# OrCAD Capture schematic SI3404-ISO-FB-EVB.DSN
size B; title: Si3402 Eval Board - Isolated; rev: 2.0; note: SI3404-ISO-FB-EVB
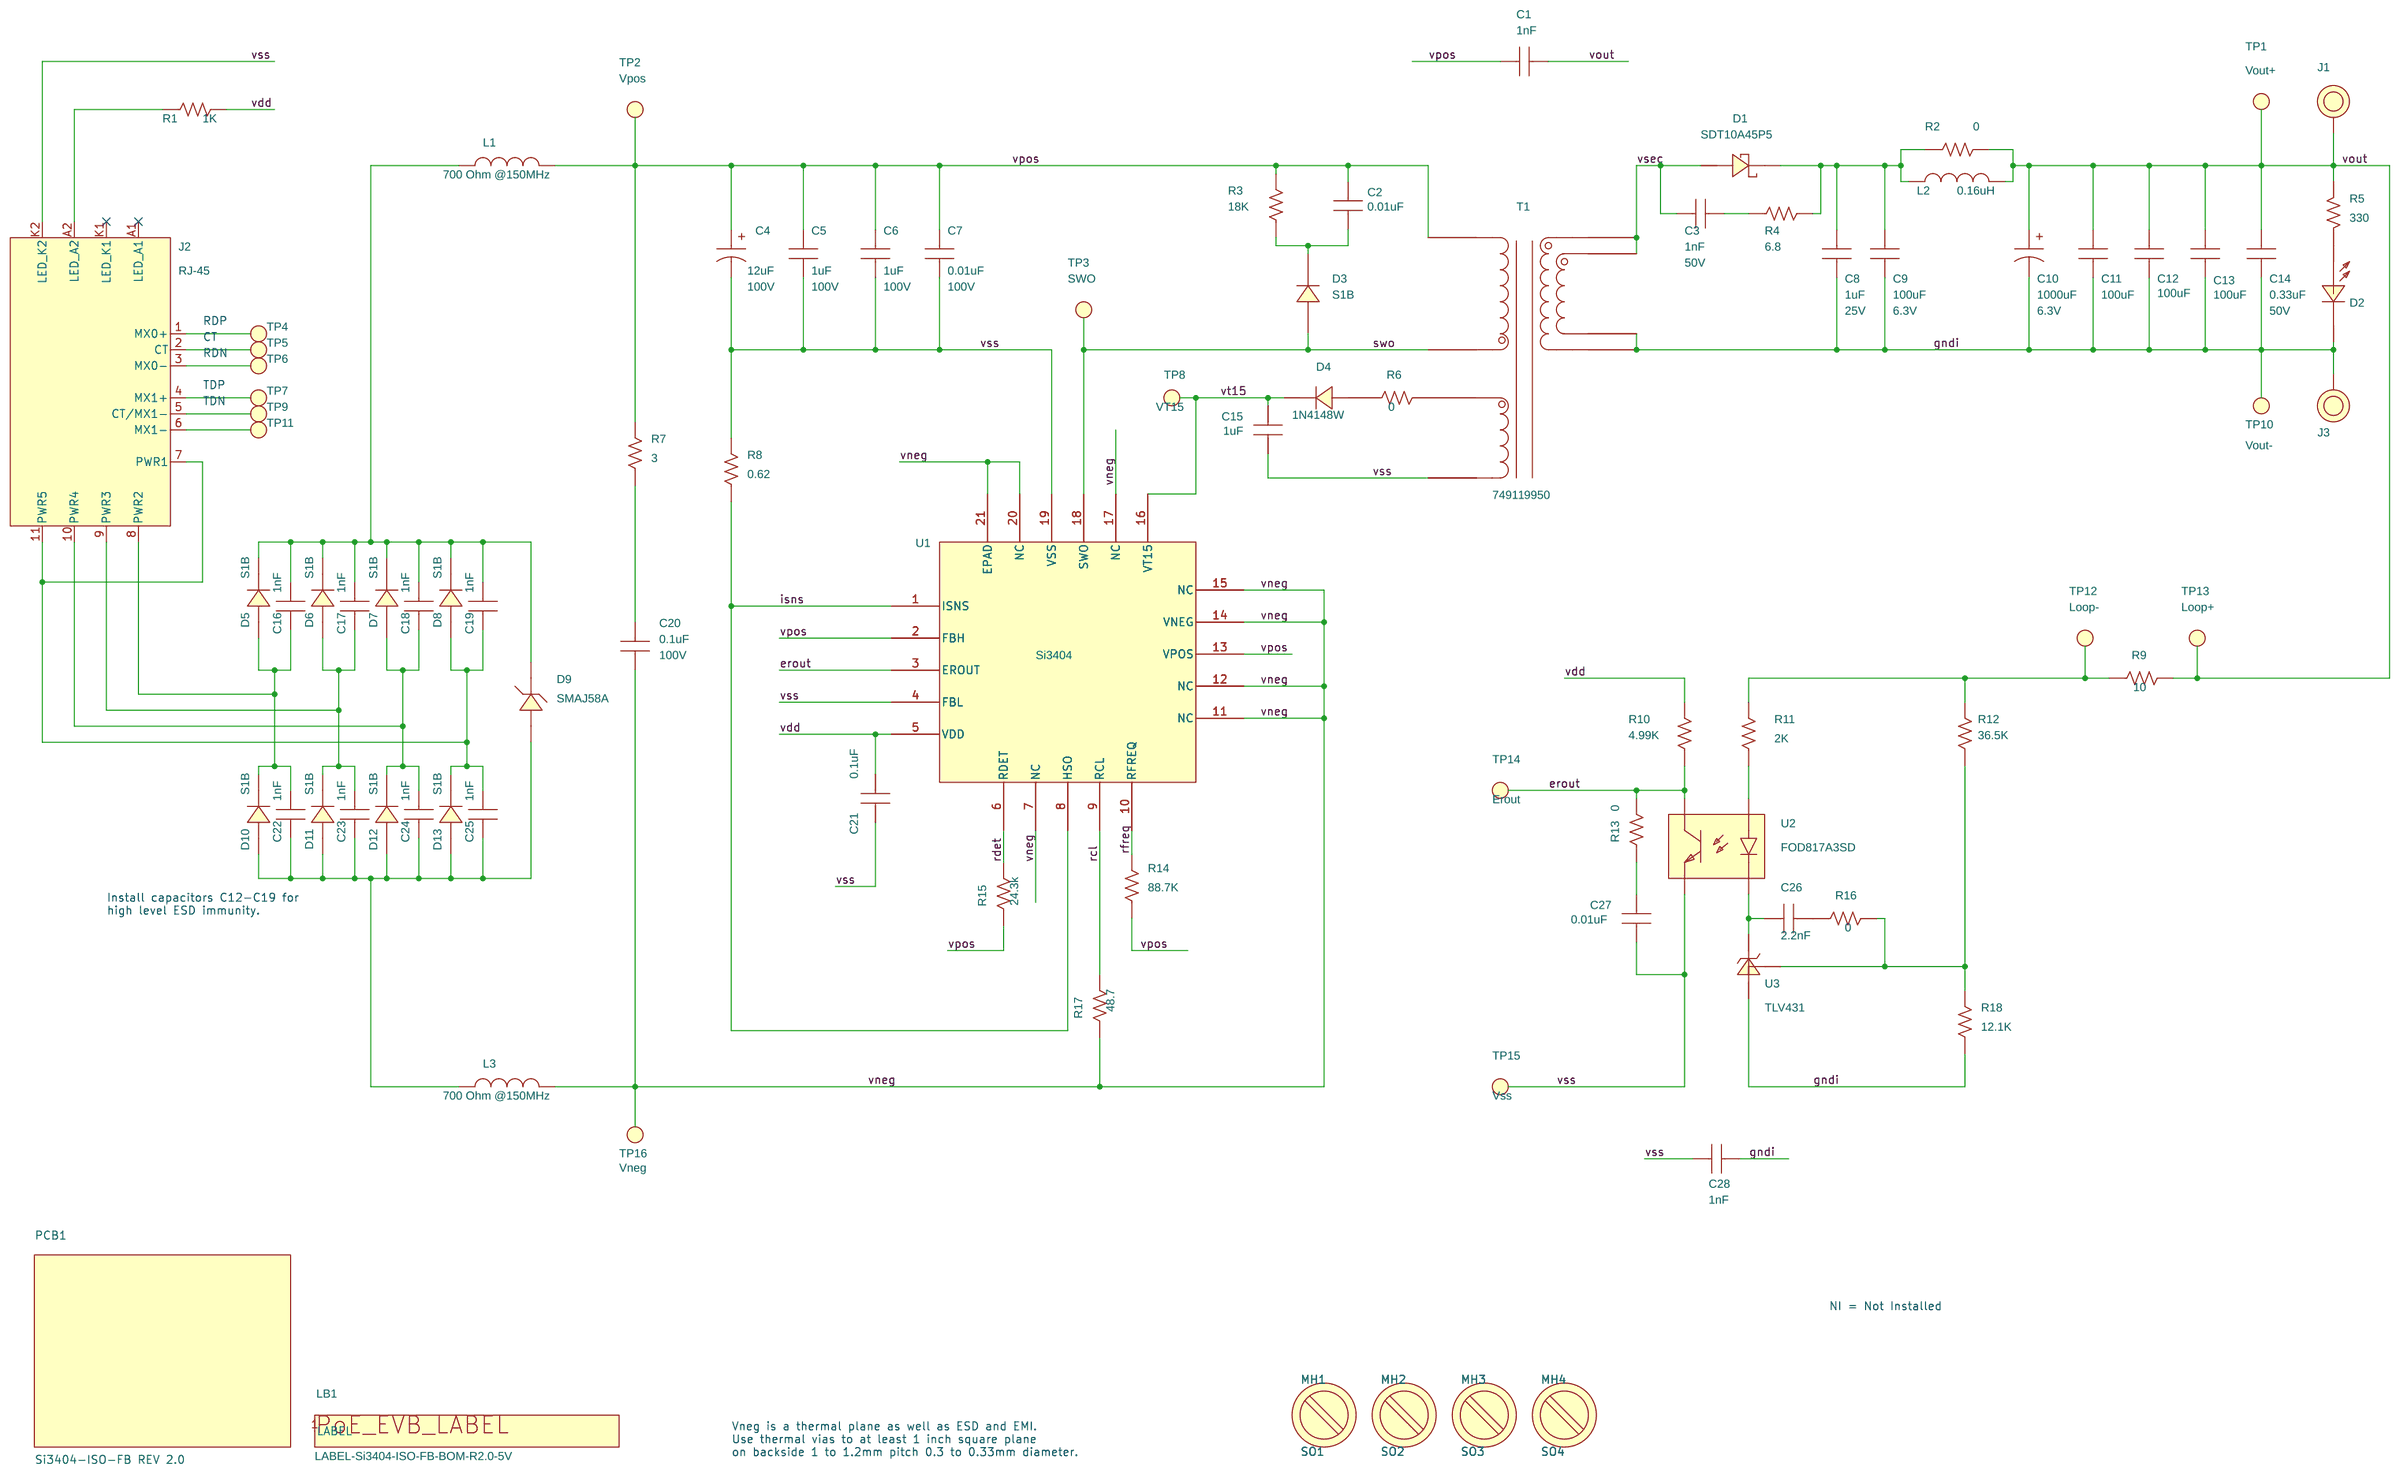
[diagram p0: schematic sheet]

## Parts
C1  1nF  [C1808]
C2  0.01uF  [C0805]
C3  1nF  [C0805]
C4  12uF  [C2.5X6.3MM-RAD]
C5  1uF  [C1210]
C6  1uF  [C1210]
C7  0.01uF  [C0603]
C8  1uF  [C0603]
C9  100uF  [C1210]
C10  1000uF  [C3.5X8MM-RAD]
C11  100uF  [C1210]
C12  100uF  [C1210]
C13  100uF  [C1210]
C14  0.33uF  [C0805]
C15  1uF  [C0805]
C16  1nF  [C0603]
C17  1nF  [C0603]
C18  1nF  [C0603]
C19  1nF  [C0603]
C20  0.1uF  [C0805]
C21  0.1uF  [C0805]
C22  1nF  [C0603]
C23  1nF  [C0603]
C24  1nF  [C0603]
C25  1nF  [C0603]
C26  2.2nF  [C0805]
C27  0.01uF  [C0805]
C28  1nF  [C1808]
D1  SDT10A45P5  [POWERDI-5]
D2  GREEN  [LED-0805-K]
D3  S1B  [DO-214AC]
D4  1N4148W  [SOD-123]
D5  S1B  [DO-214AC]
D6  S1B  [DO-214AC]
D7  S1B  [DO-214AC]
D8  S1B  [DO-214AC]
D9  SMAJ58A  [DO-214AC]
D10  S1B  [DO-214AC]
D11  S1B  [DO-214AC]
D12  S1B  [DO-214AC]
D13  S1B  [DO-214AC]
J1  BND_POST  [BANANA-JACK]
J2  RJ-45  [RJ45-SI-52004]
J3  BND_POST  [BANANA-JACK]
L1  742792040  [L0805]
L2  0.16uH  [IND-XAL50xx]
L3  742792040  [L0805]
LB1  LABEL-Si3404-ISO-FB-BOM-R2.0-5V  [PTL-14-717]
MH1  4-40  [MH-125NP]
MH2  4-40  [MH-125NP]
MH3  4-40  [MH-125NP]
MH4  4-40  [MH-125NP]
PCB1  Si3404-ISO-FB REV 2.0  [N/A]
R1  1K  [R0805]
R2  0  [R0805]
R3  18K  [R0805]
R4  6.8  [R0805]
R5  330  [R0805]
R6  0  [R0805]
R7  3  [R0805]
R8  0.62  [R0805]
R9  10  [R0805]
R10  4.99K  [R0805]
R11  2K  [R0805]
R12  36.5K  [R0805]
R13  0  [R0805]
R14  88.7K  [R0805]
R15  24.3k  [R0805]
R16  0  [R0805]
R17  48.7  [R0805]
R18  12.1K  [R0805]
SO1  STANDOFF
SO2  STANDOFF
SO3  STANDOFF
SO4  STANDOFF
T1  127uH  [XFMR-749119950]
TP1  BLACK  [TESTPOINT]
TP2  BLACK  [TESTPOINT]
TP3  BLACK  [TESTPOINT]
TP4  BLACK  [TESTPOINT]
TP5  BLACK  [TESTPOINT]
TP6  BLACK  [TESTPOINT]
TP7  BLACK  [TESTPOINT]
TP8  BLACK  [TESTPOINT]
TP9  BLACK  [TESTPOINT]
TP10  BLACK  [TESTPOINT]
TP11  BLACK  [TESTPOINT]
TP12  BLACK  [TESTPOINT]
TP13  BLACK  [TESTPOINT]
TP14  BLACK  [TESTPOINT]
TP15  BLACK  [TESTPOINT]
TP16  BLACK  [TESTPOINT]
U1  Si3404  [QFN20M4X4P0.5]
U2  FOD817A3SD  [SO4N10.16P2.54-AKEC]
U3  TLV431  [TLV431-DBZ]

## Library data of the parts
C1 C28 = CAP_NP: CAP, 1nF, 3000V, ±10%, X7R, 1808; Manufacturer: Venkel; ManufacturerPN: C1808X7R302-102K; SiLabsPN: C1808X7R302-102K; Tolerance: ±10%; Type: X7R; Voltage: 3000V; Datasheet: PID_C.pdf
C2 C27 = CAP_NP: CAP, 0.01uF, 100V, ±10%, X7R, 0805; Manufacturer: Venkel; ManufacturerPN: C0805X7R101-103K; SiLabsPN: C0805X7R101-103K; Tolerance: ±10%; Type: X7R; Voltage: 100V; Datasheet: PID_C.pdf
C3 = CAP_NP: CAP, 1nF, 50V, ±1%, C0G, 0805; Manufacturer: Venkel; ManufacturerPN: C0805C0G500-102F; SiLabsPN: C0805C0G500-102F; Tolerance: ±1%; Type: C0G; Voltage: 50V; Datasheet: PID_C.pdf
C4 = CAP_POL_ALT: CAP, 12uF, 100V, ±20%, AL, 6.3X11.2MM; Manufacturer: Panasonic; ManufacturerPN: EEUFC2A120; SiLabsPN: EEUFC2A120; Tolerance: ±20%; Type: Alum_Elec; Voltage: 100V; Datasheet: ABA0000CE22.pdf
C5 C6 = CAP_NP: CAP, 1uF, 100V, ±10%, X7R, 1210; Manufacturer: Venkel; ManufacturerPN: C1210X7R101-105K; SiLabsPN: C1210X7R101-105K; Tolerance: ±10%; Type: X7R; Voltage: 100V; Datasheet: PID_C.pdf
C7 = CAP_NP: CAP, 0.01uF, 100V, ±10%, X7R, 0603; Manufacturer: Venkel; ManufacturerPN: C0603X7R101-103K; SiLabsPN: C0603X7R101-103K; Tolerance: ±10%; Type: X7R; Voltage: 100V; Datasheet: PID_C.pdf
C8 = CAP_NP: CAP, 1uF, 25V, ±10%, X5R, 0603; Manufacturer: Venkel; ManufacturerPN: C0603X5R250-105K; SiLabsPN: C0603X5R250-105K; Tolerance: ±10%; Type: X5R; Voltage: 25V; Datasheet: PID_C.pdf
C9 C11-C13 = CAP_NP: CAP, 100uF, 6.3V, ±10%, X5R, 1210; Manufacturer: Venkel; ManufacturerPN: C1210X5R6R3-107K; SiLabsPN: C1210X5R6R3-107K; Tolerance: ±10%; Type: X5R; Voltage: 6.3V; Datasheet: PID_C.pdf
C10 = CAP_POL_ALT: CAP, 1000uF, 6.3V, ±20%, AL, 8X11.5MM; Manufacturer: Panasonic; ManufacturerPN: ECA0JM102; SiLabsPN: ECA0JM102; Tolerance: ±20%; Type: Alum_Elec; Voltage: 6.3V; Datasheet: ABA0000CE12.pdf
C14 = CAP_NP: CAP, 0.33uF, 50V, ±10%, X7R, 0805; Manufacturer: Venkel; ManufacturerPN: C0805X7R500-334K; SiLabsPN: C0805X7R500-334K; Tolerance: ±10%; Type: X7R; Voltage: 50V; Datasheet: PID_C.pdf
C15 = CAP_NP: CAP, 1uF, 50V, ±10%, X7R, 0805; Manufacturer: Samsung; ManufacturerPN: CL21B105KBFNNNE; SiLabsPN: C0805X7R500-105K; Tolerance: ±10%; Type: X7R; Voltage: 50V; Datasheet: CL21B105KBFNNNE.pdf
C16-C19 C22-C25 = CAP_NP: CAP, 1nF, 100V, ±10%, X7R, 0603; Manufacturer: Venkel; ManufacturerPN: C0603X7R101-102K; SiLabsPN: C0603X7R101-102K; Tolerance: ±10%; Type: X7R; Voltage: 100V; Datasheet: PID_C.pdf
C20 = CAP_NP: CAP, 0.1uF, 100V, ±10%, X7R, 0805; Manufacturer: Venkel; ManufacturerPN: C0805X7R101-104K; SiLabsPN: C0805X7R101-104K; Tolerance: ±10%; Type: X7R; Voltage: 100V; Datasheet: PID_C.pdf
C21 = CAP_NP: CAP, 0.1uF, 16V, ±10%, X7R, 0805; Manufacturer: Venkel; ManufacturerPN: C0805X7R160-104K; SiLabsPN: C0805X7R160-104K; Tolerance: ±10%; Type: X7R; Voltage: 16V; Datasheet: PID_C.pdf
C26 = CAP_NP: CAP, 2.2nF, 50V, ±10%, C0G, 0805; Manufacturer: Venkel; ManufacturerPN: C0805C0G500-222K; SiLabsPN: C0805C0G500-222K; Tolerance: ±10%; Type: C0G; Voltage: 50V; Datasheet: PID_C.pdf
D1 = DIODE_SCHOTTKY_DUAL_ANODE_3PIN: DIO, SCHOTTKY, 45V, 10A, PowerDI-5; Manufacturer: Diodes Inc.; ManufacturerPN: SDT10A45P5-7; Rating: 10A; SiLabsPN: SDT10A45P5-7; Type: Schottky; Voltage: 45V; Datasheet: SDT10A45P5.pdf
D2 = LED: LED, GREEN, 0805; Manufacturer: LITE_ON INC; ManufacturerPN: LTST-C170GKT; Rating: 30mA; SiLabsPN: LTST-C170GKT; Type: SMT; Voltage: 2.2V; Datasheet: LTST-C170GKT.pdf
D3 D5-D8 D10-D13 = DIODE: DIO, SINGLE, 100V, 1.0A, SMA; Manufacturer: Fairchild; Rating: 1.0A; Type: Single; Voltage: 100V; Datasheet: S1A.pdf
D4 = DIODE: DIO, SINGLE, 100V, 300mA, SOD123; Manufacturer: Diodes Inc.; ManufacturerPN: 1N4148W-7-F; Rating: 300mA; SiLabsPN: 1N4148W-7-F; Type: Single; Voltage: 100V; Datasheet: ds30086.pdf
D9 = DIODE_ZENER: DIO, TVS, UNIDIR, 58V, 400W; Manufacturer: Littelfuse; Rating: 400W; Type: GP; Voltage: 58V; Datasheet: smaj.pdf
J1 = BINDING-POST: CONN, BANANA JACK, Threaded uninsulated; Manufacturer: ABBATRON HH SMITH; ManufacturerPN: 101; Rating: 15A; SiLabsPN: 101; Silk: +; Type: BANANA; Datasheet: SD-101.pdf
J2 = MAGJACK_3: CONN, RJ-45, MAGJACK, 1 Port PoE; Manufacturer: Bel; ManufacturerPN: SI-52003-F; SiLabsPN: SI-52003-F; Type: Receptacle; Datasheet: SI-52003-F.pdf
J3 = BINDING-POST: CONN, BANANA JACK, Threaded uninsulated; Manufacturer: ABBATRON HH SMITH; ManufacturerPN: 101; Rating: 15A; SiLabsPN: 101; Type: BANANA; Datasheet: SD-101.pdf
L1 L3 = Ferrite_Bead: FERRITE BEAD, 700 Ohm @150MHZ, 0805; Manufacturer: Wurth; Rating: 2000mA; Type: SMT; Voltage: 700 Ohm @150MHz; Datasheet: 742792040.pdf
L2 = INDUCTOR: INDUCTOR, POWER, Shielded, 0.16uH, 31A, SMD; Manufacturer: Coilcraft; ManufacturerPN: XAL5030-161ME; Rating: 16A; SiLabsPN: XAL5030-161ME; Tolerance: ±20%; Type: Shielded; Datasheet: xal50xx-270657.pdf
LB1 = PoE_EVB_Label: LABEL, PDB, POLYIMIDE, WHITE, 1.00 in. X 0.187 in., FONT 2; Manufacturer: Skyworks; Type: POLYIMIDE, WHITE; Datasheet: Brady TLS2200 Label PTL-14-717.pdf
MH1-MH4 = SCREW-Small: HDW, SCREW, 4-40 x 1/4 in. Pan Head, Slotted, Nylon; Manufacturer: Richco Plastic Co; ManufacturerPN: NSS-4-4-01; SiLabsPN: NSS-4-4-01; Type: SCREW; Datasheet: RichcoPlasticCo_Screws.pdf
PCB1 = PCB: PCB, BARE BOARD, Si3404-ISO-FB REV 2.0; Manufacturer: Skyworks; Type: BARE PCB
R1 = RES: RES, 1K, 1/10W, ±1%, ThickFilm, 0805; Manufacturer: Venkel; ManufacturerPN: CR0805-10W-1001F; Rating: 1/10W; SiLabsPN: CR0805-10W-1001F; Tolerance: ±1%; Type: ThickFilm; Datasheet: PID_CR.pdf
R2 = RES: RES, 0 Ohm, 6A, ThickFilm, 0805; Manufacturer: Vishay Dale; ManufacturerPN: CRCW08050000Z0EAHP; Rating: 6A; SiLabsPN: CRCW08050000Z0EAHP; Type: ThickFilm; Datasheet: crcwhpe3.pdf
R3 = RES: RES, 18K, 1/10W, ±5%, ThickFilm, 0805; Manufacturer: Venkel; ManufacturerPN: CR0805-10W-183J; Rating: 1/10W; SiLabsPN: CR0805-10W-183J; Tolerance: ±5%; Type: ThickFilm; Datasheet: PID_CR.pdf
R4 = RES: RES, 6.8 Ohm, 1/8W, ±1%, ThickFilm, 0805; Manufacturer: Yageo; ManufacturerPN: RC0805FR-076R8L; Rating: 1/8W; SiLabsPN: CR0805-8W-6R80F; Tolerance: ±1%; Type: ThickFilm; Datasheet: PID_CR.pdf
R5 = RES: RES, 330 Ohm, 1/10W, ±1%, ThickFilm, 0805; Manufacturer: Venkel; ManufacturerPN: CR0805-10W-3300F; Rating: 1/10W; SiLabsPN: CR0805-10W-3300F; Tolerance: ±1%; Type: ThickFilm; Datasheet: PID_CR.pdf
R6 R13 R16 = RES: RES, 0 Ohm, 2A, ThickFilm, 0805; Manufacturer: Venkel; ManufacturerPN: CR0805-10W-000; Rating: 2A; SiLabsPN: CR0805-10W-000; Type: ThickFilm; Datasheet: PID_CR.pdf
R7 = RES: RES, 3 Ohm, 1/8W, ±1%, ThickFilm, 0805; Manufacturer: Venkel; ManufacturerPN: CR0805-8W-3R00FT; Rating: 1/8W; SiLabsPN: CR0805-8W-3R00F; Tolerance: ±1%; Type: ThickFilm; Datasheet: PID_CR.pdf
R8 = RES: RES, 0.62 Ohm, 1/8W, ±1%, ThickFilm, 0805; Manufacturer: Yageo; ManufacturerPN: RL0805FR-070R62L; Rating: 1/8W; SiLabsPN: CR0805-8W-R620F; Tolerance: ±1%; Type: ThickFilm; Datasheet: PYu-RL_Group_521_RoHS_L 1.pdf
R9 = RES: RES, 10 Ohm, 1/10W, ±1%, ThickFilm, 0805; Manufacturer: Venkel; ManufacturerPN: CR0805-10W-10R0F; Rating: 1/10W; SiLabsPN: CR0805-10W-10R0F; Tolerance: ±1%; Type: ThickFilm; Datasheet: PID_CR.pdf
R10 = RES: RES, 4.99K, 1/10W, ±1%, ThickFilm, 0805; Manufacturer: Venkel; ManufacturerPN: CR0805-10W-4991F; Rating: 1/10W; SiLabsPN: CR0805-10W-4991F; Tolerance: ±1%; Type: ThickFilm; Datasheet: PID_CR.pdf
R11 = RES: RES, 2K, 1/8W, ±1%, ThickFilm, 0805; Manufacturer: Venkel; ManufacturerPN: CR0805-8W-2001F; Rating: 1/8W; SiLabsPN: CR0805-8W-2001F; Tolerance: ±1%; Type: ThickFilm; Datasheet: PID_CR.pdf
R12 = RES: RES, 36.5K, 1/10W, ±1%, ThickFilm, 0805; Manufacturer: Venkel; ManufacturerPN: CR0805-10W-3652F; Rating: 1/10W; SiLabsPN: CR0805-10W-3652F; Tolerance: ±1%; Type: ThickFilm; Datasheet: PID_CR.pdf
R14 = RES: RES, 88.7K, 1/8W, ±1%, ThickFilm, 0805; Manufacturer: Vishay; ManufacturerPN: CRCW080588K7FKEA; Rating: 1/8W; SiLabsPN: CR0805-8W-8872F; Tolerance: ±1%; Type: ThickFilm; Datasheet: dcrcwe3-109170.pdf
R15 = RES: RES, 24.3k, 1/8W, ±1%, ThickFilm, 0805; Manufacturer: vishay; ManufacturerPN: CRCW080524K3FKEA; Rating: 1/8W; SiLabsPN: CR0805-8W-2432F; Tolerance: ±1%; Type: ThickFilm; Datasheet: dcrcwe3-109170.pdf
R17 = RES: RES, 48.7 Ohm, 1/8W, ±1%, ThickFilm, 0805; Manufacturer: vishay; ManufacturerPN: CRCW080548R7FKTA; Rating: 1/8W; SiLabsPN: CR0805-8W-48R7F; Tolerance: ±1%; Type: ThickFilm; Datasheet: dcrcwe3-109170.pdf
R18 = RES: RES, 12.1K, 1/10W, ±1%, ThickFilm, 0805; Manufacturer: Venkel; ManufacturerPN: CR0805-10W-1212F; Rating: 1/10W; SiLabsPN: CR0805-10W-1212F; Tolerance: ±1%; Type: ThickFilm; Datasheet: PID_CR.pdf
SO1-SO4 = STANDOFF: HDW, STANDOFF, 4-40 X 1/2" , Nylon; Manufacturer: SPC Technology; ManufacturerPN: 2397; SiLabsPN: 2397; Datasheet: SPC_Technology_spacers.pdf
T1 = 7491199xxx: TRANSFORMER, Flyback, PoE, 127uH, 15W, Aux winding, SMT; Manufacturer: Wurth Elektronik; ManufacturerPN: 749119950; Rating: 15W; SiLabsPN: 749119950; Voltage: 5V; Datasheet: 749119950.pdf
TP1 = TEST_POINT: TESTPOINT, BLACK, 0.050" LOOP, PTH; Installed Component: NI; Manufacturer: Keystone; ManufacturerPN: 5001; SiLabsPN: 5001; Silk: Vout+; Type: LOOP; Datasheet: Keystone_thm_datasheet.pdf
TP2 = TEST_POINT: TESTPOINT, BLACK, 0.050" LOOP, PTH; Manufacturer: Keystone; ManufacturerPN: 5001; SiLabsPN: 5001; Silk: Vpos; Type: LOOP; Datasheet: Keystone_thm_datasheet.pdf
TP3 = TEST_POINT: TESTPOINT, BLACK, 0.050" LOOP, PTH; Manufacturer: Keystone; ManufacturerPN: 5001; SiLabsPN: 5001; Silk: SWO; Type: LOOP; Datasheet: Keystone_thm_datasheet.pdf
TP4-TP7 TP9 TP11 = TEST_POINT: TESTPOINT, BLACK, 0.050" LOOP, PTH; Manufacturer: Keystone; ManufacturerPN: 5001; SiLabsPN: 5001; Silk: <Silk>; Type: LOOP; Datasheet: Keystone_thm_datasheet.pdf
TP8 = TEST_POINT: TESTPOINT, BLACK, 0.050" LOOP, PTH; Manufacturer: Keystone; ManufacturerPN: 5001; SiLabsPN: 5001; Silk: VT15; Type: LOOP; Datasheet: Keystone_thm_datasheet.pdf
TP10 = TEST_POINT: TESTPOINT, BLACK, 0.050" LOOP, PTH; Installed Component: NI; Manufacturer: Keystone; ManufacturerPN: 5001; SiLabsPN: 5001; Silk: Vout-; Type: LOOP; Datasheet: Keystone_thm_datasheet.pdf
TP12 = TEST_POINT: TESTPOINT, BLACK, 0.050" LOOP, PTH; Installed Component: NI; Manufacturer: Keystone; ManufacturerPN: 5001; SiLabsPN: 5001; Silk: Loop-; Type: LOOP; Datasheet: Keystone_thm_datasheet.pdf
TP13 = TEST_POINT: TESTPOINT, BLACK, 0.050" LOOP, PTH; Installed Component: NI; Manufacturer: Keystone; ManufacturerPN: 5001; SiLabsPN: 5001; Silk: Loop+; Type: LOOP; Datasheet: Keystone_thm_datasheet.pdf
TP14 = TEST_POINT: TESTPOINT, BLACK, 0.050" LOOP, PTH; Installed Component: NI; Manufacturer: Keystone; ManufacturerPN: 5001; SiLabsPN: 5001; Silk: Erout; Type: LOOP; Datasheet: Keystone_thm_datasheet.pdf
TP15 = TEST_POINT: TESTPOINT, BLACK, 0.050" LOOP, PTH; Installed Component: NI; Manufacturer: Keystone; ManufacturerPN: 5001; SiLabsPN: 5001; Silk: Vss; Type: LOOP; Datasheet: Keystone_thm_datasheet.pdf
TP16 = TEST_POINT: TESTPOINT, BLACK, 0.050" LOOP, PTH; Manufacturer: Keystone; ManufacturerPN: 5001; SiLabsPN: 5001; Silk: Vneg; Type: LOOP; Datasheet: Keystone_thm_datasheet.pdf
U1 = Si3404: IC, FULLY-INTEGRATED 802.3-COMPLIANT PoE PD INTERFACE AND LOW-EMI SWITCHING REGULATOR, QFN20; Manufacturer: Skyworks; ManufacturerPN: Si3404-A-GM; SiLabsPN: Si3404-A-GM; Type: PD; Voltage: 120V; Datasheet: Si3404.pdf
U2 = OPTOCOUPLER: PHOTOCOUPLER, 5000Vrms Isolation, 4-PIN SMD; Manufacturer: Vishay; Datasheet: FOD814-D.PDF
U3 = SHUNT_REG: IC, ADJ PREC SHUNT REG LV SOT-23 Voltage-Output 1.24 ~ 6V; Manufacturer: TI; ManufacturerPN: TLV431BCDBZR; SiLabsPN: TLV431BCDBZR; Type: SHUNT; Datasheet: tlv431a.pdf

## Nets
gndi: C8.2 C9.2 C10.2 C11.2 C12.2 C13.2 C14.2 C28.2 D2.K(CATHODE) J3.1(BP) R18.1 T1.9 T1.10 TP10.1(Point) U3.A(Anode)
vdd: C21.1 R1.2 R10.2 U1.5(VDD)
vss: C4.2 C5.1 C6.1 C7.2 C15.2 C21.2 C27.2 C28.1 J2.K2(LED) R8.2 T1.1 TP15.1(Point) U1.4(FBL) U1.19(VSS) U2.E(EMITTER)
erout: R10.1 R13.2 TP14.1(Point) U1.3(EROUT) U2.C(COLLECTOR)
isns: R8.1 U1.1(ISNS) U1.8(HSO)
LABEL: LB1.1(LABEL)
rcl: R17.2 U1.9(RCL)
rdet: R15.2 U1.6(RDET)
rfreq: R14.2 U1.10(RFREQ)
swo: D3.A(ANODE) T1.3 TP3.1(Point) U1.18(SWO)
vneg: C20.2 L3.2 R17.1 TP16.1(Point) U1.7(NC) U1.11(NC) U1.12(NC) U1.14(VNEG) U1.15(NC) U1.17(NC) U1.20(NC) U1.21(EPAD)
vout: C1.2 C10.1 C11.1 C12.1 C13.1 C14.1 J1.1(BP) L2.2 R2.2 R5.2 R9.2 TP1.1(Point) TP13.1(Point)
vpos: C1.1 C2.1 C4.1 C5.2 C6.2 C7.1 L1.2 R3.2 R7.2 R14.1 R15.1 T1.4 TP2.1(Point) U1.2(FBH) U1.13(VPOS)
vsec: C3.1 D1.A1(ANODE) D1.A2(ANODE) T1.7 T1.8
vt15: C15.1 D4.K(CATHODE) TP8.1(Point) U1.16(VT15)
N82452: R12.1 R16.2 R18.2 U3.REF(VREF)
N774821: R9.1 R11.2 R12.2 TP12.1(Point)
N789722: C22.1 C23.1 C24.1 C25.1 D9.A(ANODE) D10.A(ANODE) D11.A(ANODE) D12.A(ANODE) D13.A(ANODE) L3.1
N791215: C17.1 C23.2 D6.A(ANODE) D11.K(CATHODE) J2.9(PWR3)
N792139: C18.1 C24.2 D7.A(ANODE) D12.K(CATHODE) J2.10(PWR4)
N793095: C19.1 C25.2 D8.A(ANODE) D13.K(CATHODE) J2.7(PWR1) J2.11(PWR5)
N794438: C16.1 C22.2 D5.A(ANODE) D10.K(CATHODE) J2.8(PWR2)
N797451: C16.2 C17.2 C18.2 C19.2 D5.K(CATHODE) D6.K(CATHODE) D7.K(CATHODE) D8.K(CATHODE) D9.K(CATHODE) L1.1
N857543: C26.1 U2.K(CATHODE) U3.K(Cathode)
N921627: C27.1 R13.1
N922209: R11.1 U2.A(ANODE)
N924596: C8.1 C9.1 D1.K(CATHODE) L2.1 R2.1 R4.2
N931180: J2.2(CT) TP5.1(Point)
N931186: J2.3(MX0-) TP6.1(Point)
N931192: J2.4(MX1+) TP7.1(Point)
N931211: J2.5(CT/MX1-) TP9.1(Point)
N931235: J2.1(MX0+) TP4.1(Point)
N1492597: C2.2 D3.K(CATHODE) R3.1
N1496970: J2.A2(LED) R1.1
N1503111: C3.2 R4.1
N1541338: J2.6(MX1-) TP11.1(Point)
N1547807: C20.1 R7.1
N1605454: D2.A(ANODE) R5.1
N1605455: C26.2 R16.1
N1605456: D4.A(ANODE) R6.1
N1605457: R6.2 T1.2

Not connected (* = marked no-connect by the designer): J2 A1(LED)* K1(LED)*

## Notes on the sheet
- CT
- RDP
- RDN
- TDP
- TDN
- Install capacitors C12-C19 for
  high level ESD immunity.
- NI = Not Installed
- Vneg is a thermal plane as well as ESD and EMI.
  Use thermal vias to at least 1 inch square plane
  on backside 1 to 1.2mm pitch 0.3 to 0.33mm diameter.
